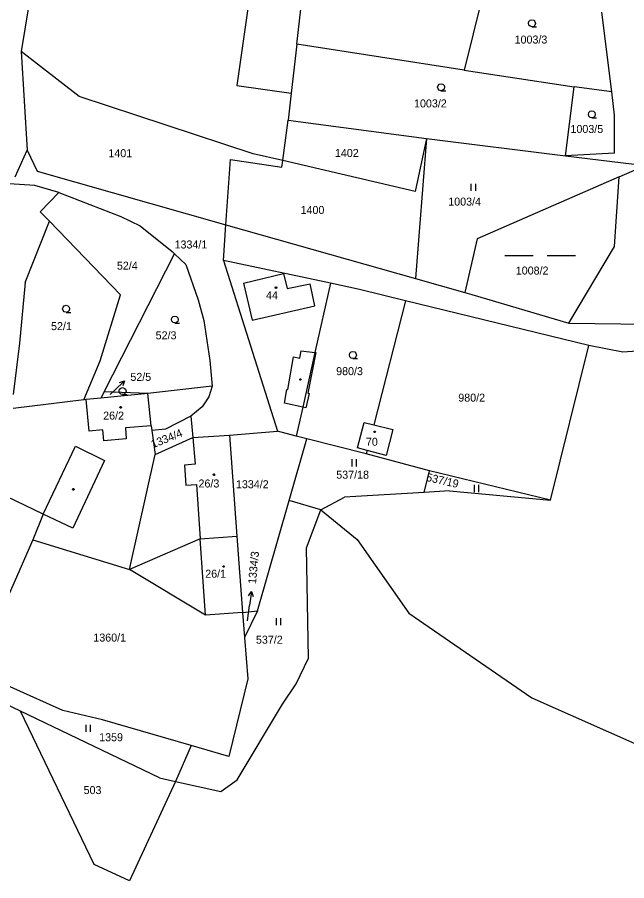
# Model space of a CAD drawing. Extents: x -845995 to -842497, y -1063614 to -1059680.
# Drawn here: x -844448.3 to -844318.8, y -1061709.6 to -1061526.1 of the extents above; entities that cross this region are included whole.
import ezdxf

# ---------------------------------------------------------------- set-up
doc = ezdxf.new("R2010")
doc.units = 0
for name, color, linetype in [('KN_HRANICE', 7, 'Continuous'), ('KN_KULTURY', 7, 'Continuous'), ('KN_PARCELY', 7, 'Continuous'), ('KN_SLUCKY', 7, 'Continuous'), ('KN_STAVEBNI', 7, 'Continuous')]:
    doc.layers.add(name, color=color, linetype=linetype)

# ---------------------------------------------------------------- blocks, each defined once
blk = doc.blocks.new('304')
blk.add_lwpolyline([(0, 0), (-0.38, 0.1), (-0.65, 0.37), (-0.75, 0.74), (-0.65, 1.11), (-0.38, 1.38), (-0.01, 1.48), (0.36, 1.38), (0.63, 1.11), (0.73, 0.73), (0.63, 0.35), (0.36, 0.08), (-0.02, -0.02), (0.98, -0.02)])
blk = doc.blocks.new('306')
for p, q in [((-0.5, 1.5), (-0.5, 0)), ((0.5, 0), (0.5, 1.5))]:
    blk.add_line(p, q)
blk = doc.blocks.new('803')
for p, q in [((-7.5, 0), (-1.5, 0)), ((1.5, 0), (7.5, 0))]:
    blk.add_line(p, q)
blk = doc.blocks.new('10292')
blk.add_line((0, 3), (0, 0))
blk.add_lwpolyline([(-0.5, 2), (0, 3), (0.5, 2)])
blk = doc.blocks.new('402')
blk.add_lwpolyline([(0.09, 0.15), (0.18, 0), (0.09, -0.15), (-0.09, -0.15), (-0.18, 0), (-0.09, 0.15), (0.09, 0.15)])

msp = doc.modelspace()

# ---------------------------------------------------------------- linework, layer by layer
at = {"layer": 'KN_HRANICE'}
for p, q in [((-844388.92, -1061531.86), (-844387.54, -1061520.17)), ((-844349.36, -1061521.16), (-844353.34, -1061537.33)), ((-844445.93, -1061523.92), (-844447.49, -1061533.39)), ((-844321.96, -1061541.94), (-844324.04, -1061525.01)), ((-844388.92, -1061531.86), (-844390.11, -1061542.25)), ((-844353.34, -1061537.33), (-844388.92, -1061531.86)), ((-844435.17, -1061542.92), (-844447.49, -1061533.39)), ((-844447.49, -1061533.39), (-844446.24, -1061554.35)), ((-844353.34, -1061537.33), (-844329.92, -1061540.93)), ((-844331.78, -1061555.55), (-844329.92, -1061540.93)), ((-844321.96, -1061541.94), (-844329.92, -1061540.93)), ((-844321.35, -1061546.91), (-844321.96, -1061541.94)), ((-844398.2, -1061555.11), (-844435.17, -1061542.92)), ((-844390.11, -1061542.25), (-844390.76, -1061547.96)), ((-844321.41, -1061554.97), (-844321.35, -1061546.91)), ((-844391.89, -1061556.58), (-844390.76, -1061547.96)), ((-844390.76, -1061547.96), (-844361.35, -1061551.88)), ((-844361.35, -1061551.88), (-844363.72, -1061563.16)), ((-844361.35, -1061551.88), (-844363.66, -1061581.64)), ((-844361.35, -1061551.88), (-844331.78, -1061555.55)), ((-844448.75, -1061560.05), (-844446.24, -1061554.35)), ((-844446.24, -1061554.35), (-844444.11, -1061558.8)), ((-844321.41, -1061554.97), (-844331.78, -1061555.55)), ((-844403.95, -1061570.2), (-844403.02, -1061556.36)), ((-844403.02, -1061556.36), (-844392.07, -1061557.99)), ((-844391.89, -1061556.58), (-844398.2, -1061555.11)), ((-844392.07, -1061557.99), (-844391.89, -1061556.58)), ((-844363.72, -1061563.16), (-844391.89, -1061556.58)), ((-844331.78, -1061555.55), (-844314.87, -1061557.58)), ((-844320.4, -1061560.02), (-844314.87, -1061557.58)), ((-844444.11, -1061558.8), (-844403.95, -1061570.2)), ((-844320.4, -1061560.02), (-844350.6, -1061573.17)), ((-844321.39, -1061574.83), (-844320.4, -1061560.02)), ((-844444.59, -1061561.88), (-844450, -1061561.52)), ((-844439.49, -1061563.31), (-844444.59, -1061561.88)), ((-844443.41, -1061567.42), (-844439.49, -1061563.31)), ((-844439.49, -1061563.31), (-844426.27, -1061568.44)), ((-844441.46, -1061569.44), (-844443.41, -1061567.42)), ((-844446.64, -1061582.48), (-844441.46, -1061569.44)), ((-844426.34, -1061585.08), (-844441.46, -1061569.44)), ((-844426.27, -1061568.44), (-844422.18, -1061570.43)), ((-844422.18, -1061570.43), (-844415.41, -1061575.89)), ((-844404.46, -1061577.82), (-844403.95, -1061570.2)), ((-844403.95, -1061570.2), (-844363.66, -1061581.64)), ((-844350.6, -1061573.17), (-844353.2, -1061584.61)), ((-844331.11, -1061591.08), (-844321.39, -1061574.83)), ((-844429.81, -1061605.69), (-844414.88, -1061576.38)), ((-844415.41, -1061575.89), (-844414.88, -1061576.38)), ((-844414.88, -1061576.38), (-844412.5, -1061578.61)), ((-844412.5, -1061578.61), (-844409.87, -1061586.18)), ((-844404.46, -1061577.82), (-844393, -1061614.07)), ((-844381.76, -1061582.63), (-844404.46, -1061577.82)), ((-844446.64, -1061582.48), (-844447.87, -1061595.38)), ((-844363.66, -1061581.64), (-844353.2, -1061584.61)), ((-844381.76, -1061582.63), (-844385.04, -1061597.34)), ((-844375.58, -1061583.94), (-844381.76, -1061582.63)), ((-844365.77, -1061586.33), (-844375.58, -1061583.94)), ((-844430.7, -1061599.13), (-844426.34, -1061585.08)), ((-844409.87, -1061586.18), (-844408.69, -1061590.57)), ((-844353.2, -1061584.61), (-844351.68, -1061585.04)), ((-844351.68, -1061585.04), (-844331.11, -1061591.08)), ((-844365.77, -1061586.33), (-844372.54, -1061612.69)), ((-844326.87, -1061595.82), (-844365.77, -1061586.33)), ((-844408.69, -1061590.57), (-844407.36, -1061599.06)), ((-844331.11, -1061591.08), (-844302.31, -1061591.53)), ((-844255.5, -1061592.46), (-844319.6, -1061597.27)), ((-844447.87, -1061595.38), (-844449.19, -1061606.24)), ((-844334.99, -1061628.71), (-844326.87, -1061595.82)), ((-844319.6, -1061597.27), (-844326.87, -1061595.82)), ((-844385.04, -1061597.34), (-844387.63, -1061608.98)), ((-844434.17, -1061607.4), (-844430.7, -1061599.13)), ((-844407.36, -1061599.06), (-844406.9, -1061604.52)), ((-844406.9, -1061604.52), (-844420.55, -1061606.03)), ((-844406.9, -1061604.52), (-844407.58, -1061606.77)), ((-844429.81, -1061605.69), (-844430.56, -1061607.03)), ((-844420.55, -1061606.03), (-844430.56, -1061607.03)), ((-844420.55, -1061606.03), (-844429.81, -1061605.69)), ((-844434.17, -1061607.4), (-844449.19, -1061609.24)), ((-844433.67, -1061607.34), (-844434.17, -1061607.4)), ((-844430.56, -1061607.03), (-844433.67, -1061607.34)), ((-844407.58, -1061606.77), (-844409.04, -1061608.91)), ((-844409.04, -1061608.91), (-844411.39, -1061610.86)), ((-844387.63, -1061608.98), (-844389, -1061615.11)), ((-844411.39, -1061610.86), (-844416.78, -1061613.62)), ((-844411.39, -1061610.86), (-844410.98, -1061615.41)), ((-844416.78, -1061613.62), (-844419.7, -1061613.9)), ((-844419.7, -1061613.9), (-844418.97, -1061619.01)), ((-844418.97, -1061619.01), (-844410.98, -1061615.41)), ((-844410.98, -1061615.41), (-844403.17, -1061614.92)), ((-844403.17, -1061614.92), (-844393, -1061614.07)), ((-844403.17, -1061614.92), (-844401.63, -1061636.37)), ((-844389, -1061615.11), (-844393, -1061614.07)), ((-844386.76, -1061615.69), (-844389, -1061615.11)), ((-844390.52, -1061628.76), (-844386.76, -1061615.69)), ((-844374.13, -1061618.87), (-844386.76, -1061615.69)), ((-844424.43, -1061643.44), (-844418.97, -1061619.01)), ((-844373.95, -1061618.15), (-844375.97, -1061617.63)), ((-844373.95, -1061618.15), (-844374.13, -1061618.87)), ((-844360.67, -1061622.48), (-844374.13, -1061618.87)), ((-844361.86, -1061627.06), (-844360.67, -1061622.48)), ((-844334.99, -1061628.71), (-844360.67, -1061622.48)), ((-844442.81, -1061631.67), (-844457.28, -1061624.8)), ((-844383.79, -1061630.77), (-844378.77, -1061628.06)), ((-844361.86, -1061627.06), (-844378.77, -1061628.06)), ((-844356.45, -1061626.74), (-844361.86, -1061627.06)), ((-844356.45, -1061626.74), (-844334.99, -1061628.71)), ((-844397.26, -1061652.22), (-844390.52, -1061628.76)), ((-844383.79, -1061630.77), (-844390.52, -1061628.76)), ((-844442.81, -1061631.67), (-844445.01, -1061637.13)), ((-844386.84, -1061638.84), (-844383.79, -1061630.77)), ((-844383.79, -1061630.77), (-844376.04, -1061637.09)), ((-844445.01, -1061637.13), (-844457.31, -1061665.08)), ((-844445.01, -1061637.13), (-844424.43, -1061643.44)), ((-844409.45, -1061636.9), (-844424.43, -1061643.44)), ((-844409.45, -1061636.9), (-844401.63, -1061636.37)), ((-844401.63, -1061636.37), (-844400.47, -1061652.6)), ((-844376.04, -1061637.09), (-844365.11, -1061652.71)), ((-844386.4, -1061662.29), (-844386.84, -1061638.84)), ((-844408.29, -1061653.16), (-844424.43, -1061643.44)), ((-844447.63, -1061673.57), (-844500.09, -1061648.51)), ((-844400.47, -1061652.6), (-844397.26, -1061652.22)), ((-844397.26, -1061652.22), (-844400.04, -1061657.86)), ((-844400.47, -1061652.6), (-844408.29, -1061653.16)), ((-844400.47, -1061652.6), (-844400.04, -1061657.86)), ((-844365.11, -1061652.71), (-844338.96, -1061670.68)), ((-844400.04, -1061657.86), (-844399.31, -1061666.7)), ((-844389.07, -1061667.77), (-844386.4, -1061662.29)), ((-844438.63, -1061673.4), (-844457.31, -1061665.08)), ((-844399.31, -1061666.7), (-844403.35, -1061683.2)), ((-844391.94, -1061672.06), (-844389.07, -1061667.77)), ((-844401.55, -1061688.12), (-844391.94, -1061672.06)), ((-844338.96, -1061670.68), (-844281.72, -1061696.14)), ((-844418.06, -1061687.7), (-844447.63, -1061673.57)), ((-844431.96, -1061706.15), (-844447.63, -1061673.57)), ((-844430.19, -1061675.35), (-844438.63, -1061673.4)), ((-844411.36, -1061680.86), (-844430.19, -1061675.35)), ((-844411.36, -1061680.86), (-844414.65, -1061688.46)), ((-844403.35, -1061683.2), (-844411.36, -1061680.86)), ((-844414.65, -1061688.46), (-844424.45, -1061709.57)), ((-844418.06, -1061687.7), (-844414.65, -1061688.46)), ((-844414.65, -1061688.46), (-844405.04, -1061690.59)), ((-844405.04, -1061690.59), (-844401.55, -1061688.12)), ((-844424.45, -1061709.57), (-844431.96, -1061706.15))]:
    msp.add_line(p, q, dxfattribs=at)
for points in [[(-844375.97, -1061617.63), (-844374.57, -1061612.18), (-844372.54, -1061612.69)], [(-844372.54, -1061612.69), (-844368.49, -1061613.72), (-844369.9, -1061619.19), (-844373.95, -1061618.15)]]:
    msp.add_lwpolyline(points, dxfattribs=at)
at = {"layer": 'KN_PARCELY'}
for p, q in [((-844428.56, -1061606.28), (-844427.68, -1061605.44)), ((-844399.36, -1061654.37), (-844398.93, -1061651.08))]:
    msp.add_line(p, q, dxfattribs=at)
at = {"layer": 'KN_SLUCKY'}
for p, q in [((-844399.03, -1061522.17), (-844401.68, -1061540.59)), ((-844401.68, -1061540.59), (-844390.11, -1061542.25)), ((-844400.24, -1061582.58), (-844391.7, -1061580.59)), ((-844391.7, -1061580.59), (-844390.96, -1061583.76)), ((-844400.24, -1061582.58), (-844398.4, -1061590.46)), ((-844390.96, -1061583.76), (-844386.07, -1061582.78)), ((-844385.09, -1061587.46), (-844386.07, -1061582.78)), ((-844398.4, -1061590.46), (-844385.09, -1061587.46)), ((-844388.27, -1061598.54), (-844387.95, -1061597.02)), ((-844387.95, -1061597.02), (-844385.04, -1061597.34)), ((-844390.81, -1061605.22), (-844389.57, -1061598.27)), ((-844389.57, -1061598.27), (-844388.27, -1061598.54)), ((-844384.89, -1061597.36), (-844386.59, -1061605.98)), ((-844385.04, -1061597.34), (-844384.89, -1061597.36)), ((-844419.85, -1061612.89), (-844420.55, -1061606.03)), ((-844391.51, -1061608.12), (-844390.99, -1061605.19)), ((-844390.99, -1061605.19), (-844390.81, -1061605.22)), ((-844386.24, -1061606.04), (-844386.99, -1061609.12)), ((-844386.59, -1061605.98), (-844386.24, -1061606.04)), ((-844433, -1061614.02), (-844433.67, -1061607.34)), ((-844387.63, -1061608.98), (-844391.51, -1061608.12)), ((-844386.99, -1061609.12), (-844387.63, -1061608.98)), ((-844419.85, -1061612.89), (-844425.33, -1061613.36)), ((-844425.33, -1061613.36), (-844425.13, -1061615.69)), ((-844419.85, -1061612.89), (-844419.7, -1061613.9)), ((-844430.09, -1061613.77), (-844433, -1061614.02)), ((-844429.89, -1061616.09), (-844430.09, -1061613.77)), ((-844410.98, -1061615.41), (-844410.49, -1061621.05)), ((-844442.81, -1061631.67), (-844435.96, -1061617.24)), ((-844435.96, -1061617.24), (-844429.76, -1061620.26)), ((-844425.13, -1061615.69), (-844429.89, -1061616.09)), ((-844429.76, -1061620.26), (-844436.5, -1061634.67)), ((-844410.49, -1061621.05), (-844412.76, -1061621.25)), ((-844412.76, -1061621.25), (-844412.46, -1061625.56)), ((-844412.46, -1061625.56), (-844410.21, -1061625.4)), ((-844410.21, -1061625.4), (-844409.45, -1061636.9)), ((-844436.5, -1061634.67), (-844442.81, -1061631.67)), ((-844408.29, -1061653.16), (-844409.45, -1061636.9))]:
    msp.add_line(p, q, dxfattribs=at)
at = {"layer": 'KN_STAVEBNI'}
for p, q in [((-844400.24, -1061582.58), (-844391.7, -1061580.59)), ((-844391.7, -1061580.59), (-844390.96, -1061583.76)), ((-844400.24, -1061582.58), (-844398.4, -1061590.46)), ((-844390.96, -1061583.76), (-844386.07, -1061582.78)), ((-844385.09, -1061587.46), (-844386.07, -1061582.78)), ((-844398.4, -1061590.46), (-844385.09, -1061587.46)), ((-844420.55, -1061606.03), (-844430.56, -1061607.03)), ((-844419.85, -1061612.89), (-844420.55, -1061606.03)), ((-844430.56, -1061607.03), (-844433.67, -1061607.34)), ((-844433, -1061614.02), (-844433.67, -1061607.34)), ((-844419.85, -1061612.89), (-844425.33, -1061613.36)), ((-844425.33, -1061613.36), (-844425.13, -1061615.69)), ((-844430.09, -1061613.77), (-844433, -1061614.02)), ((-844429.89, -1061616.09), (-844430.09, -1061613.77)), ((-844410.98, -1061615.41), (-844403.17, -1061614.92)), ((-844410.98, -1061615.41), (-844410.49, -1061621.05)), ((-844403.17, -1061614.92), (-844401.63, -1061636.37)), ((-844425.13, -1061615.69), (-844429.89, -1061616.09)), ((-844373.95, -1061618.15), (-844375.97, -1061617.63)), ((-844410.49, -1061621.05), (-844412.76, -1061621.25)), ((-844412.76, -1061621.25), (-844412.46, -1061625.56)), ((-844412.46, -1061625.56), (-844410.21, -1061625.4)), ((-844410.21, -1061625.4), (-844409.45, -1061636.9)), ((-844409.45, -1061636.9), (-844401.63, -1061636.37)), ((-844409.45, -1061636.9), (-844401.63, -1061636.37)), ((-844408.29, -1061653.16), (-844409.45, -1061636.9)), ((-844401.63, -1061636.37), (-844400.47, -1061652.6)), ((-844400.47, -1061652.6), (-844408.29, -1061653.16))]:
    msp.add_line(p, q, dxfattribs=at)
for points in [[(-844375.97, -1061617.63), (-844374.57, -1061612.18), (-844372.54, -1061612.69)], [(-844372.54, -1061612.69), (-844368.49, -1061613.72), (-844369.9, -1061619.19), (-844373.95, -1061618.15)]]:
    msp.add_lwpolyline(points, dxfattribs=at)

# ---------------------------------------------------------------- block references
at = {"layer": 'KN_KULTURY'}
for name, p in [('304', (-844338.91, -1061528.14)), ('304', (-844358.24, -1061541.71)), ('304', (-844326.19, -1061547.48)), ('306', (-844351.38, -1061563)), ('803', (-844337.19, -1061576.75)), ('402', (-844393.34, -1061583.56)), ('304', (-844437.93, -1061588.79)), ('304', (-844414.81, -1061591.07)), ('304', (-844376.96, -1061598.61)), ('402', (-844388.12, -1061603.08)), ('304', (-844425.93, -1061606.27)), ('402', (-844426.32, -1061608.99)), ('402', (-844372.37, -1061614.17)), ('306', (-844376.68, -1061621.53)), ('402', (-844406.53, -1061623.29)), ('402', (-844436.41, -1061626.42)), ('306', (-844350.69, -1061626.99)), ('402', (-844404.47, -1061642.81)), ('306', (-844392.82, -1061655.28)), ('306', (-844433.21, -1061677.96))]:
    msp.add_blockref(name, p, dxfattribs=at)
at = {"layer": 'KN_PARCELY'}
for p, rotation in [((-844427.68, -1061605.44), -46.36290299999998), ((-844398.93, -1061651.08), -7.3444769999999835)]:
    msp.add_blockref('10292', p, dxfattribs=dict(at, rotation=rotation))

# ---------------------------------------------------------------- texts
for s, height, p in [('1003/3', 1.7, (-844342.61, -1061531.7)), ('1003/2', 1.7, (-844363.98, -1061545.27)), ('1003/5', 1.7, (-844330.74, -1061550.7)), ('1401', 1.7, (-844428.94, -1061555.84)), ('1402', 1.7, (-844380.8, -1061555.8)), ('1003/4', 1.7, (-844356.71, -1061566.13)), ('1400', 1.7, (-844388.1, -1061567.91)), ('1334/1', 1.7, (-844414.88, -1061575.24)), ('52/4', 1.7, (-844427.13, -1061579.74)), ('1008/2', 1.7, (-844342.36, -1061580.78)), ('44', 1.7, (-844395.44, -1061586.03)), ('52/1', 1.7, (-844441.13, -1061592.59)), ('52/3', 1.7, (-844418.9, -1061594.54)), ('980/3', 1.7, (-844380.54, -1061602.15)), ('52/5', 1.7, (-844424.27, -1061603.37)), ('52/5', 0.1, (-844428.76, -1061606.28)), ('980/2', 1.7, (-844354.58, -1061607.78)), ('26/2', 1.7, (-844430.05, -1061611.6)), ('70', 1.7, (-844374.21, -1061617.16)), ('537/18', 1.7, (-844380.51, -1061624.15)), ('26/3', 1.7, (-844409.79, -1061626.02)), ('1334/2', 1.7, (-844401.83, -1061626.18)), ('26/1', 1.7, (-844408.36, -1061645.19)), ('1334/3', 0.1, (-844399.66, -1061654.37)), ('1360/1', 1.7, (-844432.14, -1061658.76)), ('537/2', 1.7, (-844397.58, -1061659.21)), ('1359', 1.7, (-844430.9, -1061679.93)), ('503', 1.7, (-844434.21, -1061691.16))]:
    msp.add_text(s, height=height, dxfattribs=at).set_placement(p)
for s, rotation, p in [('1334/4', 22.059, (-844419.47, -1061617.7)), ('537/19', 347.155, (-844361.51, -1061624.59)), ('1334/3', 84.454, (-844397.59, -1061646.58))]:
    msp.add_text(s, height=1.7, rotation=rotation, dxfattribs=at).set_placement(p)

doc.saveas('drawing.dxf')
